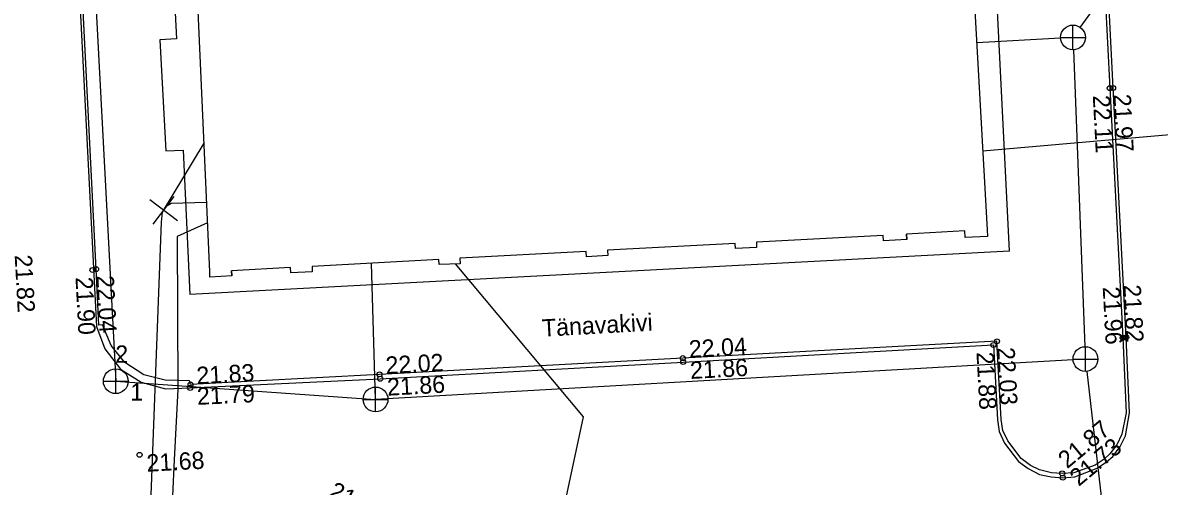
# Model space of a CAD drawing. Extents: x 714038 to 714279, y 6589845 to 6590041.
# Drawn here: x 714116.25 to 714162.18, y 6589987.15 to 6590005.87 of the extents above; entities that cross this region are included whole.
import ezdxf

# ---------------------------------------------------------------- set-up
doc = ezdxf.new("R2010")
doc.units = 0
for name, color, linetype in [('HOONE', 7, 'Continuous'), ('HOONEDET', 7, 'Continuous'), ('KORGUS', 7, 'Continuous'), ('MPKAABEL', 7, 'Continuous'), ('SITRASS', 7, 'Continuous'), ('SKKAEV', 7, 'Continuous'), ('SKTRASS', 7, 'Continuous'), ('TEE', 7, 'Continuous'), ('TORU NR', 7, 'Continuous'), ('VTRASS', 7, 'Continuous')]:
    doc.layers.add(name, color=color, linetype=linetype)

msp = doc.modelspace()

# ---------------------------------------------------------------- linework, layer by layer
at = {"layer": 'HOONE'}
for points in [[(714153.616, 6590026.033), (714155.226, 6589997.511), (714155.241, 6589997.24), (714154.336, 6589997.193), (714154.321, 6589997.462), (714151.965, 6589997.335), (714151.976, 6589997.121), (714151.028, 6589997.067), (714151.016, 6589997.283), (714145.894, 6589997.006), (714145.906, 6589996.793), (714145.055, 6589996.75), (714145.043, 6589996.96), (714139.884, 6589996.681), (714139.884, 6589996.675), (714139.895, 6589996.469), (714139.031, 6589996.422), (714139.02, 6589996.634), (714133.911, 6589996.358), (714133.923, 6589996.136), (714133.072, 6589996.104), (714133.061, 6589996.312), (714127.939, 6589996.034), (714127.951, 6589995.815), (714127.082, 6589995.772), (714127.07, 6589995.987), (714124.685, 6589995.858), (714124.697, 6589995.649), (714123.815, 6589995.597), (714123.806, 6589995.811)], [(714123.806, 6589995.811), (714122.528, 6590024.418)], [(714155.223, 6589997.511), (714155.226, 6589997.511)], [(714151.976, 6589997.121), (714151.965, 6589997.335)], [(714139.031, 6589996.422), (714139.02, 6589996.634)], [(714123.806, 6589995.811), (714123.828, 6589995.812)], [(714124.697, 6589995.649), (714124.685, 6589995.858)], [(714127.082, 6589995.772), (714127.07, 6589995.987)]]:
    msp.add_lwpolyline(points, dxfattribs=at)
at = {"layer": 'HOONEDET'}
for points in [[(714134.084, 6590025.899), (714120.754, 6590025.223), (714120.927, 6590021.387), (714121.652, 6590021.434), (714122.002, 6590014.168), (714122.456, 6590005.222), (714121.784, 6590005.188), (714122.031, 6590000.695), (714122.737, 6590000.728), (714122.997, 6589994.9)], [(714156.127, 6589996.644), (714155.189, 6590015.256), (714154.783, 6590023.3), (714154.78, 6590023.348)], [(714156.127, 6589996.644), (714140.34, 6589995.813), (714122.997, 6589994.9)]]:
    msp.add_lwpolyline(points, dxfattribs=at)
at = {"layer": 'KORGUS'}
for centre in [(714160.175, 6590003.23), (714160.313, 6590003.239), (714119.066, 6589995.885), (714119.214, 6589995.92), (714155.474, 6589992.859), (714155.618, 6589993.007), (714160.699, 6589993.151), (714160.841, 6589993.165), (714142.927, 6589992.328), (714142.938, 6589992.169), (714130.67, 6589991.672), (714130.695, 6589991.494), (714123.012, 6589991.123), (714123.027, 6589991.258), (714120.971, 6589988.421), (714158.255, 6589987.67), (714158.276, 6589987.496)]:
    msp.add_circle(centre, 0.1, dxfattribs=at)
at = {"layer": 'MPKAABEL'}
msp.add_lwpolyline([(714123.717, 6589997.796), (714122.485, 6589997.244), (714122.51, 6589991.06), (714122.373, 6589988.225), (714122.093, 6589982.401), (714122.625, 6589980.577), (714131.807, 6589975.295), (714155.806, 6589963.558), (714167.836, 6589958.048), (714177.51, 6589953.25), (714191.113, 6589945.528), (714192.794, 6589944.261), (714190.81, 6589933.623), (714190.196, 6589929.064), (714190.863, 6589919.753), (714192.278, 6589911.176), (714192.96, 6589897.79), (714194.31, 6589864.41), (714194.86, 6589849.85), (714194.551, 6589845.18)], dxfattribs=at)
at = {"layer": 'SITRASS'}
for p, q in [((714121.524, 6589997.736), (714122.364, 6589998.856)), ((714122.504, 6589997.876), (714121.384, 6589998.716))]:
    msp.add_line(p, q, dxfattribs=at)
for points in [[(714037.81, 6590017.083), (714041.45, 6590015.4), (714049.64, 6590011.61), (714053.69, 6590009.84), (714078.46, 6589999.77), (714120.53, 6589982.37), (714120.99, 6589982.37), (714121.09, 6589982.42), (714121.19, 6589982.57), (714121.29, 6589982.87), (714121.49, 6589988.215), (714121.85, 6589997.82), (714121.9, 6589998.22), (714123.574, 6590001.009)], [(714122.05, 6589998.47), (714122.25, 6589998.58), (714123.68, 6589998.626)]]:
    msp.add_lwpolyline(points, dxfattribs=at)
at = {"layer": 'SKKAEV'}
for p, q in [((714158.689, 6590004.781), (714158.689, 6590005.781)), ((714158.189, 6590005.281), (714159.189, 6590005.281)), ((714159.192, 6589991.789), (714159.192, 6589992.789)), ((714158.692, 6589992.289), (714159.692, 6589992.289)), ((714120.007, 6589990.894), (714120.007, 6589991.894)), ((714119.507, 6589991.394), (714120.507, 6589991.394)), ((714130.507, 6589990.159), (714130.507, 6589991.159)), ((714130.007, 6589990.659), (714131.007, 6589990.659))]:
    msp.add_line(p, q, dxfattribs=at)
for centre in [(714158.689, 6590005.281), (714159.192, 6589992.289), (714120.007, 6589991.394), (714130.507, 6589990.659)]:
    msp.add_circle(centre, 0.5, dxfattribs=at)
at = {"layer": 'SKTRASS'}
for points in [[(714117.671, 6590035.609), (714120.007, 6589991.394)], [(714158.983, 6590005.685), (714168.6, 6590018.903)], [(714158.19, 6590005.253), (714154.8, 6590005.061)], [(714158.708, 6590004.781), (714159.173, 6589992.789)], [(714130.507, 6589990.659), (714130.338, 6589996.164)], [(714158.693, 6589992.261), (714130.507, 6589990.659)], [(714159.249, 6589991.792), (714159.833, 6589986.731)], [(714120.007, 6589991.394), (714130.507, 6589990.659)]]:
    msp.add_lwpolyline(points, dxfattribs=at)
at = {"layer": 'TEE'}
for p, q in [((714159.328, 6590020.072), (714160.175, 6590003.23)), ((714119.214, 6589995.92), (714118.575, 6590008.805)), ((714160.175, 6590003.23), (714160.699, 6589993.151)), ((714119.323, 6589993.653), (714119.214, 6589995.92)), ((714119.477, 6589993.678), (714119.323, 6589993.653)), ((714119.822, 6589992.834), (714119.477, 6589993.678)), ((714155.618, 6589993.007), (714142.927, 6589992.328)), ((714155.785, 6589989.849), (714155.618, 6589993.007)), ((714160.699, 6589993.151), (714160.835, 6589990.121)), ((714120.372, 6589992.151), (714119.822, 6589992.834)), ((714121.138, 6589991.653), (714120.372, 6589992.151)), ((714142.927, 6589992.328), (714130.67, 6589991.672)), ((714122.002, 6589991.439), (714121.138, 6589991.653)), ((714130.67, 6589991.672), (714123.027, 6589991.258)), ((714122.985, 6589991.411), (714122.002, 6589991.439)), ((714123.027, 6589991.258), (714122.985, 6589991.411)), ((714160.835, 6589990.121), (714160.668, 6589989.251)), ((714155.858, 6589989.403), (714155.785, 6589989.849)), ((714156.052, 6589988.992), (714155.858, 6589989.403)), ((714160.668, 6589989.251), (714160.458, 6589988.818)), ((714156.599, 6589988.269), (714156.052, 6589988.992)), ((714160.458, 6589988.818), (714160.176, 6589988.467)), ((714160.176, 6589988.467), (714159.947, 6589988.249)), ((714156.975, 6589987.988), (714156.599, 6589988.269)), ((714157.336, 6589987.809), (714156.975, 6589987.988)), ((714159.584, 6589988.004), (714158.718, 6589987.694)), ((714159.947, 6589988.249), (714159.584, 6589988.004)), ((714157.815, 6589987.697), (714157.336, 6589987.809)), ((714158.255, 6589987.67), (714157.815, 6589987.697)), ((714158.718, 6589987.694), (714158.255, 6589987.67))]:
    msp.add_line(p, q, dxfattribs=at)
for points in [[(714118.17, 6590040.965), (714117.844, 6590040.591), (714117.445, 6590039.93), (714117.134, 6590039.169), (714116.988, 6590038.386), (714116.932, 6590037.581), (714117.045, 6590035.166), (714117.725, 6590022.434), (714118.442, 6590008.801), (714119.224, 6589993.603), (714119.563, 6589992.698), (714120.198, 6589991.881), (714121.032, 6589991.362), (714122.012, 6589991.089), (714123.012, 6589991.123), (714130.695, 6589991.494), (714142.938, 6589992.169), (714155.474, 6589992.859)], [(714155.474, 6589992.859), (714155.637, 6589989.831), (714155.711, 6589989.359), (714155.917, 6589988.897), (714156.482, 6589988.156), (714156.88, 6589987.871), (714157.331, 6589987.632), (714157.808, 6589987.528), (714158.276, 6589987.496), (714158.764, 6589987.53), (714159.668, 6589987.878), (714160.04, 6589988.133), (714160.305, 6589988.353), (714160.603, 6589988.76), (714160.81, 6589989.189), (714160.975, 6589990.123), (714160.841, 6589993.165), (714160.313, 6590003.239), (714159.469, 6590020.069), (714158.792, 6590033.69), (714158.488, 6590039.922), (714158.196, 6590040.965)]]:
    msp.add_lwpolyline(points, dxfattribs=at)
at = {"layer": 'VTRASS'}
for points in [[(714163.993, 6590001.465), (714155.047, 6590000.681)], [(714133.719, 6589996.129), (714138.897, 6589989.951), (714136.917, 6589980.705)]]:
    msp.add_lwpolyline(points, dxfattribs=at)

# ---------------------------------------------------------------- texts
at = {"layer": 'KORGUS'}
for s, rotation, p in [(' 22.11', 273.0002, (714159.476, 6590003.193)), (' 21.97', 273.0002, (714160.313, 6590003.239)), (' 21.82', 273.1102, (714115.908, 6589996.746)), (' 22.04', 272.9455, (714119.214, 6589995.92)), (' 21.90', 272.9455, (714118.367, 6589995.849)), (' 21.96', 273.0002, (714159.877, 6589995.456)), (' 21.82', 273.0002, (714160.716, 6589995.542)), (' 22.04', 3.0625, (714142.927, 6589992.328)), (' 22.02', 3.0636, (714130.67, 6589991.672)), (' 21.88', 273.0271, (714154.775, 6589992.822)), (' 22.03', 273.0271, (714155.618, 6589993.007)), (' 21.83', 3.1005, (714123.027, 6589991.258)), (' 21.86', 3.0625, (714142.975, 6589991.47)), (' 21.86', 3.0636, (714130.732, 6589990.795)), (' 21.79', 2.7646, (714123.046, 6589990.424)), (' 21.87', 39.6991, (714158.255, 6589987.67)), (' 21.73', 39.6991, (714158.723, 6589986.957)), (' 21.68', 3.1005, (714121.009, 6589987.722)), (' 21.67', 331.9065, (714128.33, 6589986.876))]:
    msp.add_text(s, height=0.7, rotation=rotation, dxfattribs=at).set_placement(p)
at = {"layer": 'TEE'}
msp.add_text('Tänavakivi', height=0.7, rotation=3.1505, dxfattribs=at).set_placement((714137.252, 6589993.191))
at = {"layer": 'TORU NR'}
for s, p in [('2', (714119.987, 6589992.14)), ('1', (714120.595, 6589990.611))]:
    msp.add_text(s, height=0.7, dxfattribs=at).set_placement(p)

doc.saveas('drawing.dxf')
